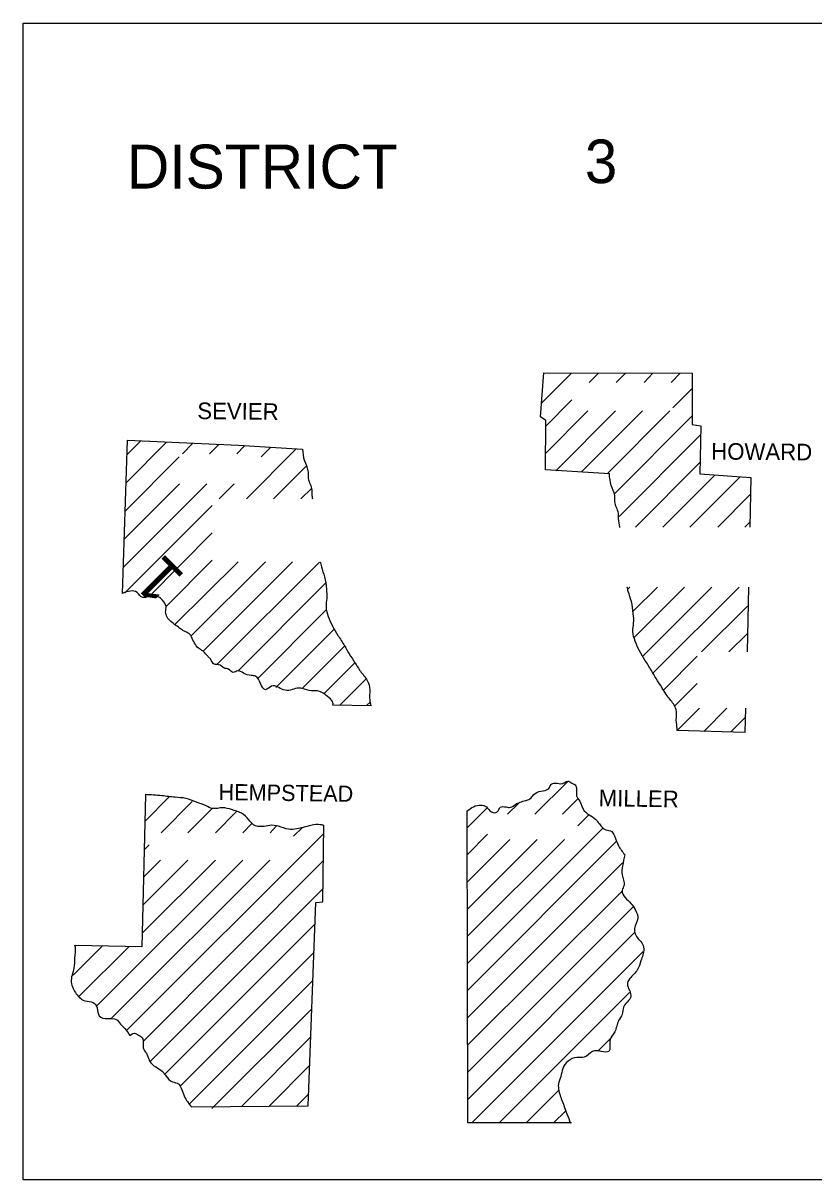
# Model space of a CAD drawing. Extents: x 21307 to 29830, y 1322443 to 1332359.
# Drawn here: x 27550.2 to 27755.3, y 1327036.8 to 1327336.8 of the extents above; entities that cross this region are included whole.
import ezdxf

# ---------------------------------------------------------------- set-up
doc = ezdxf.new("R2010")
doc.units = 0
doc.layers.add('R_Draft', color=7, linetype='Continuous')

msp = doc.modelspace()

# ---------------------------------------------------------------- linework, layer by layer
at = {"layer": 'R_Draft'}
msp.add_line((27719.9, 1327153.35), (27719.8, 1327155.05), dxfattribs=at)
msp.add_lwpolyline([(27550.24, 1327036.83), (27550.24, 1327336.83), (27950.24, 1327336.83), (27950.24, 1327036.83)], close=True, dxfattribs=at)
for points in [[(27685.7, 1327220.95), (27685.8, 1327233.75), (27684.4, 1327234.75), (27685.3, 1327246.15), (27723.8, 1327246.05)], [(27684.7, 1327238.25), (27692.5, 1327246.05)], [(27685.3, 1327245.95), (27685.4, 1327246.05)], [(27697.1, 1327243.65), (27699.5, 1327246.05)], [(27704.1, 1327243.65), (27706.5, 1327246.05)], [(27711.3, 1327243.65), (27713.6, 1327246.05)], [(27718.3, 1327243.65), (27720.7, 1327246.05)], [(27723.8, 1327246.05), (27723.8, 1327232.75), (27726, 1327232.35), (27725.8, 1327219.95), (27739, 1327218.95), (27738.7, 1327206.15)], [(27718.8, 1327237.05), (27723.8, 1327242.05)], [(27685.7, 1327232.25), (27692.6, 1327239.15)], [(27685.7, 1327225.25), (27696.7, 1327236.25)], [(27688.4, 1327220.75), (27703.9, 1327236.25)], [(27695, 1327220.35), (27710.9, 1327236.25)], [(27701.7, 1327219.95), (27718, 1327236.25)], [(27703.6, 1327214.75), (27723.8, 1327234.95)], [(27704.8, 1327208.85), (27725.9, 1327230.05)], [(27576, 1327188.95), (27577.3, 1327228.65)], [(27577, 1327217.65), (27587.4, 1327228.15)], [(27577.3, 1327228.65), (27606.1, 1327227.35)], [(27577.3, 1327225.05), (27580.7, 1327228.45)], [(27591.6, 1327225.15), (27594.2, 1327227.85)], [(27598.6, 1327225.15), (27601, 1327227.55)], [(27605.7, 1327225.15), (27607.7, 1327227.25)], [(27606.1, 1327227.35), (27622.7, 1327226.35)], [(27576.8, 1327210.35), (27590.7, 1327224.35)], [(27608.2, 1327213.45), (27621.1, 1327226.45)], [(27612, 1327224.35), (27614.4, 1327226.75)], [(27615.2, 1327213.45), (27623.6, 1327221.85)], [(27709.1, 1327206.15), (27725.8, 1327222.85)], [(27702.3, 1327219.95), (27685.7, 1327220.95)], [(27716.2, 1327206.15), (27729.7, 1327219.65)], [(27723.2, 1327206.15), (27736.2, 1327219.15)], [(27576.3, 1327195.75), (27597.9, 1327217.35)], [(27576.5, 1327203.05), (27590.8, 1327217.35)], [(27601.1, 1327213.45), (27605, 1327217.35)], [(27622.3, 1327213.45), (27625.1, 1327216.25)], [(27730.4, 1327206.15), (27738.9, 1327214.65)], [(27576.6, 1327189.05), (27599.3, 1327211.75)], [(27737.4, 1327206.15), (27738.7, 1327207.45)], [(27582.8, 1327188.05), (27599.3, 1327204.65)], [(27587.3, 1327185.55), (27599.3, 1327197.55)], [(27589.6, 1327180.85), (27606, 1327197.15)], [(27593.8, 1327177.95), (27613.1, 1327197.15)], [(27596.9, 1327173.95), (27620.1, 1327197.15)], [(27600.6, 1327170.55), (27627.1, 1327197.05)], [(27605.9, 1327168.75), (27628.7, 1327191.55)], [(27707.1, 1327190.05), (27707.6, 1327190.55)], [(27708.5, 1327184.35), (27714.8, 1327190.55)], [(27708.8, 1327177.55), (27721.8, 1327190.55)], [(27711, 1327172.65), (27728.9, 1327190.55)], [(27713.6, 1327168.25), (27736, 1327190.55)], [(27738.4, 1327190.55), (27738, 1327173.75)], [(27726.2, 1327173.75), (27738.1, 1327185.65)], [(27611.1, 1327166.85), (27628.8, 1327184.65)], [(27615.8, 1327164.55), (27630.9, 1327179.65)], [(27733.3, 1327173.75), (27738, 1327178.45)], [(27622.6, 1327164.25), (27633.6, 1327175.25)], [(27628.3, 1327162.95), (27636.3, 1327170.95)], [(27716.4, 1327163.95), (27725.1, 1327172.65)], [(27632.4, 1327159.95), (27639.2, 1327166.75)], [(27719.3, 1327159.75), (27725.1, 1327165.55)], [(27640.5, 1327159.75), (27630.6, 1327159.95)], [(27639.3, 1327159.85), (27640.3, 1327160.85)], [(27719.9, 1327153.35), (27725.7, 1327159.15)], [(27737.6, 1327159.15), (27737.4, 1327152.85), (27719.9, 1327153.35)], [(27726.8, 1327153.15), (27732.8, 1327159.15)], [(27733.8, 1327153.05), (27737.6, 1327156.85)], [(27683, 1327131.65), (27691.6, 1327140.25)], [(27582, 1327136.65), (27581, 1327097.25), (27563.7, 1327097.65)], [(27581.8, 1327129.75), (27588.1, 1327136.15)], [(27586, 1327126.85), (27594.1, 1327134.95)], [(27675.9, 1327131.65), (27678.8, 1327134.55)], [(27690.1, 1327131.65), (27694.2, 1327135.75)], [(27593, 1327126.85), (27599.3, 1327133.15)], [(27600.1, 1327126.85), (27605.6, 1327132.35)], [(27665.4, 1327128.15), (27670.6, 1327133.35)], [(27692.5, 1327051.65), (27665.6, 1327051.65), (27665.4, 1327132.55)], [(27694.1, 1327128.65), (27697.1, 1327131.55)], [(27607.2, 1327126.85), (27609.6, 1327129.25)], [(27614.3, 1327126.85), (27615.9, 1327128.55)], [(27620.4, 1327125.95), (27622.7, 1327128.25)], [(27624.2, 1327056.05), (27626.2, 1327108.75), (27628, 1327108.95), (27628.2, 1327128.85)], [(27665.5, 1327092.95), (27700.7, 1327128.15)], [(27577.1, 1327075.65), (27628.2, 1327126.65)], [(27665.4, 1327121.15), (27670.7, 1327126.45)], [(27665.5, 1327100.05), (27690.7, 1327125.15)], [(27665.5, 1327107.05), (27683.6, 1327125.15)], [(27665.5, 1327114.15), (27676.5, 1327125.15)], [(27581.6, 1327122.45), (27582.9, 1327123.75)], [(27665.5, 1327085.95), (27704.1, 1327124.55)], [(27569.3, 1327081.85), (27607.2, 1327119.75)], [(27573.2, 1327078.75), (27614.2, 1327119.75)], [(27581.1, 1327100.85), (27600.1, 1327119.75)], [(27581.3, 1327108.05), (27593, 1327119.75)], [(27581.4, 1327115.25), (27585.9, 1327119.75)], [(27581.4, 1327072.75), (27628.1, 1327119.55)], [(27665.5, 1327078.85), (27705.7, 1327119.05)], [(27583.3, 1327067.65), (27628, 1327112.35)], [(27665.6, 1327071.85), (27705.6, 1327111.75)], [(27665.6, 1327064.75), (27708.5, 1327107.65)], [(27587, 1327064.25), (27626, 1327103.25)], [(27665.6, 1327057.65), (27708.9, 1327101.05)], [(27563.2, 1327089.95), (27570.8, 1327097.55)], [(27564.7, 1327084.35), (27577.7, 1327097.35)], [(27591, 1327061.15), (27625.7, 1327095.85)], [(27666.6, 1327051.65), (27711.1, 1327096.05)], [(27593.3, 1327056.45), (27625.4, 1327088.55)], [(27673.7, 1327051.65), (27707.5, 1327085.45)], [(27599.2, 1327055.35), (27599.7, 1327055.85), (27625.1, 1327081.15)], [(27607, 1327055.95), (27624.8, 1327073.85)], [(27699.3, 1327070.25), (27702.9, 1327073.85)], [(27614.1, 1327056.05), (27624.6, 1327066.55)], [(27621.2, 1327056.05), (27624.3, 1327059.15)], [(27680.7, 1327051.65), (27689.1, 1327060.05)], [(27593.9, 1327055.75), (27624.2, 1327056.05)], [(27687.8, 1327051.65), (27691, 1327054.75)]]:
    msp.add_lwpolyline(points, dxfattribs=at)
for points in [[(27622.7, 1327226.35), (27623.2, 1327223.35), (27624.1, 1327220.75), (27624.2, 1327218.75), (27625.1, 1327215.75), (27625.1, 1327214.65), (27625.3, 1327213.45)], [(27705, 1327206.05), (27705, 1327206.15), (27704.7, 1327208.25), (27704.7, 1327209.35), (27703.8, 1327212.35), (27703.7, 1327214.35), (27702.8, 1327216.95), (27702.3, 1327219.95)], [(27627.3, 1327197.15), (27627.6, 1327195.85), (27628.4, 1327193.25), (27628.9, 1327190.05), (27629, 1327187.65), (27628.8, 1327185.45), (27629.4, 1327182.95), (27630.5, 1327180.45), (27631.9, 1327178.05), (27633.6, 1327175.35), (27634.8, 1327173.25), (27636.3, 1327170.95), (27637.5, 1327169.05), (27639.3, 1327166.65), (27640.1, 1327164.65), (27640.1, 1327161.85), (27640.4, 1327159.75)], [(27630.6, 1327159.95), (27630.6, 1327160.55), (27629.6, 1327161.85), (27628.1, 1327163.05), (27626.5, 1327163.65), (27625, 1327163.65), (27622.6, 1327164.25), (27621.3, 1327164.35), (27619.6, 1327163.85), (27617.7, 1327163.95), (27614.7, 1327164.85), (27613.1, 1327163.95), (27611.8, 1327165.55), (27610.5, 1327167.45), (27609.4, 1327167.65), (27607.4, 1327168.25), (27605.9, 1327168.85), (27604.7, 1327168.45), (27603.5, 1327169.25), (27602.4, 1327169.55), (27600.9, 1327170.45), (27599.8, 1327170.55), (27598.8, 1327171.95), (27598.2, 1327172.55), (27596.9, 1327173.95), (27595.7, 1327174.75), (27594.7, 1327176.05), (27593.9, 1327177.65), (27593.7, 1327178.05), (27591.7, 1327179.35), (27590.5, 1327180.15), (27589.2, 1327181.15), (27588, 1327182.15), (27587.3, 1327183.45), (27587.2, 1327184.05), (27587.3, 1327185.55), (27586.4, 1327187.15), (27585.3, 1327188.05), (27583.8, 1327188.15), (27582.2, 1327187.95), (27581.3, 1327187.85), (27579.8, 1327189.15), (27576, 1327188.95)], [(27719.8, 1327155.05), (27719.7, 1327155.45), (27719.7, 1327158.25), (27718.9, 1327160.25), (27717.1, 1327162.65), (27715.9, 1327164.55), (27714.4, 1327166.85), (27713.2, 1327168.95), (27711.5, 1327171.65), (27710.1, 1327174.05), (27709, 1327176.55), (27708.4, 1327179.05), (27708.6, 1327181.25), (27708.5, 1327183.65), (27708, 1327186.85), (27707.2, 1327189.45), (27706.9, 1327190.55)], [(27665.4, 1327132.55), (27668.9, 1327134.05), (27670.4, 1327133.55), (27671.7, 1327132.25), (27673.2, 1327132.25), (27674, 1327133.45), (27675.5, 1327133.55), (27676.7, 1327133.45), (27678, 1327134.25), (27679.1, 1327134.75), (27680.6, 1327135.25), (27681.7, 1327135.65), (27682.7, 1327136.75), (27684.5, 1327137.65), (27686.6, 1327138.35), (27687.2, 1327139.35), (27688.2, 1327139.75), (27690.2, 1327139.65), (27691.5, 1327140.25), (27692.6, 1327139.75), (27693.6, 1327139.05), (27693.8, 1327136.45), (27694.6, 1327135.05), (27695.8, 1327132.55), (27697.5, 1327131.25), (27699.1, 1327129.95), (27699.7, 1327129.15), (27701.4, 1327127.65), (27702.9, 1327127.15), (27703.6, 1327126.05), (27704.7, 1327123.45), (27706.3, 1327121.15)], [(27628.2, 1327128.75), (27627.4, 1327128.95), (27624.9, 1327128.75), (27622.9, 1327128.25), (27621.2, 1327127.85), (27619.1, 1327127.75), (27616.5, 1327128.55), (27614.2, 1327128.75), (27612.3, 1327128.45), (27610, 1327128.95), (27608.8, 1327130.25), (27606.9, 1327131.95), (27604.3, 1327132.85), (27602, 1327133.35), (27599.3, 1327133.15), (27597.7, 1327133.85), (27595.2, 1327134.75), (27592.4, 1327135.75), (27589.7, 1327136.05), (27586.2, 1327136.45), (27581.9, 1327136.75)], [(27706.3, 1327121.15), (27705.7, 1327118.25), (27705.6, 1327115.95), (27706.1, 1327113.25), (27705.6, 1327111.95), (27706.4, 1327110.05), (27707.9, 1327108.55), (27709, 1327106.95), (27709.7, 1327104.65), (27708.8, 1327102.05), (27709.8, 1327099.35), (27710.7, 1327098.35), (27711.2, 1327096.75), (27710.5, 1327093.65), (27709.6, 1327091.35), (27707.6, 1327089.05), (27707, 1327087.95), (27707.3, 1327086.45), (27707.8, 1327084.05), (27707.3, 1327083.35), (27706, 1327081.65), (27705.6, 1327079.75), (27704.7, 1327078.15), (27703.7, 1327075.25), (27702.4, 1327072.85), (27702.2, 1327070.15), (27700.2, 1327070.15), (27697.9, 1327070.15), (27695.8, 1327068.65), (27693.9, 1327068.55), (27691.6, 1327067.65), (27690.2, 1327065.75), (27689.7, 1327063.65), (27689.1, 1327061.65), (27689.7, 1327058.25), (27690.6, 1327055.85), (27691.3, 1327053.95), (27692.2, 1327051.55)], [(27563.6, 1327097.75), (27563.7, 1327097.25), (27563.6, 1327094.35), (27563.4, 1327091.75), (27562.7, 1327088.15), (27563.2, 1327086.45), (27565.1, 1327083.95), (27566.3, 1327083.25), (27568.4, 1327082.85), (27569.4, 1327081.45), (27570, 1327079.35), (27572.1, 1327078.65), (27574.4, 1327078.45), (27575.5, 1327077.25), (27577, 1327075.65), (27577.9, 1327074.25)], [(27577.9, 1327074.25), (27579.1, 1327074.85), (27580.2, 1327074.35), (27581.2, 1327073.65), (27581.4, 1327071.05), (27582.2, 1327069.65), (27583.4, 1327067.15), (27585.1, 1327065.85), (27586.7, 1327064.55), (27587.3, 1327063.75), (27589, 1327062.25), (27590.5, 1327061.75), (27591.2, 1327060.65), (27592.3, 1327058.05), (27593.9, 1327055.75)]]:
    msp.add_spline(points, degree=3, dxfattribs=at)

# ---------------------------------------------------------------- texts
for s, height, p in [('DISTRICT', 11.4, (27577.14, 1327293.93)), ('3', 11.3, (27695.94, 1327295.33))]:
    msp.add_text(s, height=height, dxfattribs=at).set_placement(p)
for s, height, rotation, p in [('SEVIER', 4.301, 359.4271, (27595.4, 1327234.15)), ('HOWARD', 4.301, 359.5145, (27728.7, 1327223.65)), ('1', 11.4, 135, (27592.5, 1327193.35)), ('HEMPSTEAD', 4.199, 359.1885, (27600.9, 1327135.35)), ('MILLER', 4.3, 359.1319, (27699.5, 1327133.75))]:
    msp.add_text(s, height=height, rotation=rotation, dxfattribs=at).set_placement(p)

doc.saveas('drawing.dxf')
